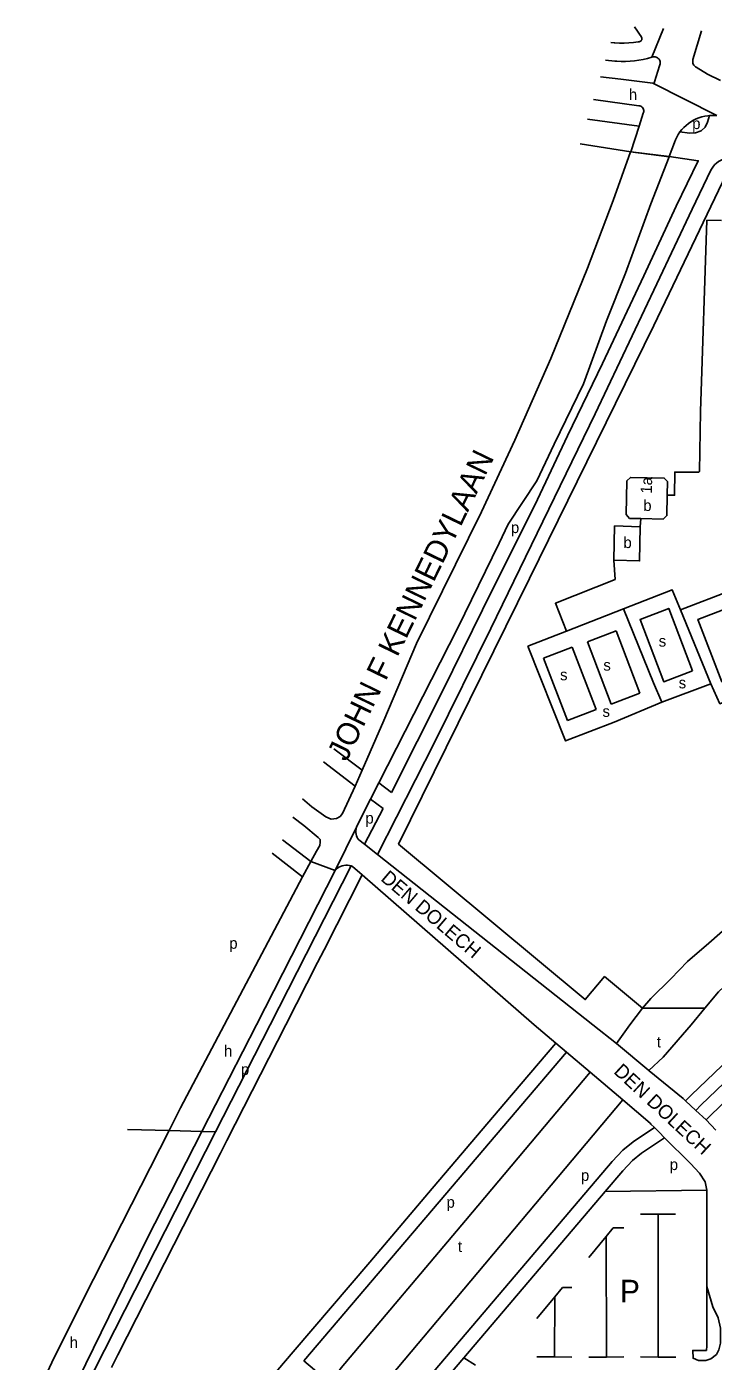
# Model space of a CAD drawing. Extents: x 161494 to 163033, y 383688 to 384862.
# Drawn here: x 161560.3 to 161805.5, y 384379.7 to 384856.8 of the extents above; entities that cross this region are included whole.
import ezdxf

# ---------------------------------------------------------------- set-up
doc = ezdxf.new("R2010")
doc.units = 0
for name, color, linetype in [('BLT_Basislijn', 7, 'Continuous'), ('BLT_Bebouwing', 7, 'Continuous'), ('BLT_Centroide', 7, 'Continuous'), ('BLT_Huisnummer', 7, 'Continuous'), ('BLT_Straatnaam', 7, 'Continuous'), ('BLT_Straatnaam_hoofdweg', 7, 'Continuous'), ('BLT_Tekst_parkeren', 7, 'Continuous'), ('BLT_Vlakafsluiter', 7, 'Continuous')]:
    doc.layers.add(name, color=color, linetype=linetype)

msp = doc.modelspace()

# ---------------------------------------------------------------- linework, layer by layer
at = {"layer": 'BLT_Basislijn'}
for p, q in [((161779.17, 384854.17), (161779.74, 384853.35)), ((161798.25, 384845.07), (161801.3, 384855.35)), ((161768.89, 384851.2), (161770.12, 384851.08)), ((161766.99, 384844.85), (161770.4, 384844.56)), ((161786.33, 384842.83), (161784.51, 384837.11)), ((161762.76, 384830.78), (161778.88, 384828.53)), ((161780.48, 384825.89), (161778.98, 384821.27)), ((161760.64, 384823.71), (161778.98, 384821.27)), ((161778.98, 384821.27), (161776.02, 384812.08)), ((161791.65, 384815.42), (161789.72, 384810.39)), ((161757.99, 384814.89), (161776.02, 384812.08)), ((161776, 384812.03), (161769.81, 384794.69)), ((161776.02, 384812.08), (161776, 384812.03)), ((161789.7, 384810.34), (161783.24, 384793.49)), ((161789.72, 384810.39), (161789.7, 384810.34)), ((161784.28, 384750), (161810.11, 384804.01)), ((161798.01, 384791.56), (161804.65, 384805.55)), ((161783.24, 384793.49), (161774.11, 384768.68)), ((161792.26, 384792.71), (161780.69, 384767.81)), ((161798.01, 384791.56), (161785.37, 384764.86)), ((161739.86, 384659.59), (161784.28, 384750)), ((161723.06, 384648.3), (161742.73, 384687.85)), ((161726.01, 384641.71), (161748.8, 384688.54)), ((161779.43, 384678.07), (161779.62, 384680.98)), ((161811.74, 384655.29), (161793.85, 384648.38)), ((161773.49, 384648.66), (161753.04, 384640.72)), ((161773.49, 384648.66), (161784.17, 384622.22)), ((161793.85, 384648.38), (161804.61, 384621.95)), ((161686.08, 384586.53), (161714.22, 384641.88)), ((161770.81, 384640.85), (161760.56, 384636.95)), ((161779.3, 384618.55), (161770.81, 384640.85)), ((161755.14, 384634.99), (161744.9, 384631.08)), ((161763.64, 384612.68), (161755.14, 384634.99)), ((161760.56, 384636.95), (161769.05, 384614.65)), ((161744.9, 384631.08), (161753.39, 384608.78)), ((161769.05, 384614.65), (161779.3, 384618.55)), ((161770.09, 384608.25), (161787.19, 384615.3)), ((161753.39, 384608.78), (161763.64, 384612.68)), ((161670.01, 384598.69), (161680.05, 384590.98)), ((161666.31, 384593.96), (161677.54, 384585.27)), ((161677.54, 384585.27), (161680.05, 384590.98)), ((161683.1, 384580.67), (161686.08, 384586.53)), ((161686.08, 384586.53), (161690.53, 384583.1)), ((161677.54, 384585.27), (161673.11, 384575.6)), ((161658.83, 384580.84), (161662.16, 384577.93)), ((161678.33, 384571.22), (161683.1, 384580.67)), ((161687.6, 384577.29), (161680.87, 384564.52)), ((161683.1, 384580.67), (161687.6, 384577.29)), ((161655.34, 384574.19), (161659.2, 384571.26)), ((161678.33, 384571.22), (161678.05, 384570.66)), ((161651.65, 384566.08), (161661.72, 384558.44)), ((161678.87, 384566.1), (161680.87, 384564.52)), ((161680.87, 384564.52), (161685.54, 384560.83)), ((161647.98, 384561.33), (161658.72, 384552.92)), ((161661.72, 384558.44), (161658.72, 384552.92)), ((161685.54, 384560.83), (161762.52, 384500)), ((161670.48, 384555.12), (161642.33, 384500)), ((161676.12, 384556.78), (161647.22, 384500)), ((161680.09, 384553.57), (161666.47, 384526.8)), ((161676.67, 384556.55), (161676.12, 384556.78)), ((161680.09, 384553.57), (161676.67, 384556.55)), ((161741.54, 384500), (161680.09, 384553.57)), ((161658.72, 384552.92), (161615.23, 384470.27)), ((161666.47, 384526.8), (161664.14, 384522.22)), ((161664.14, 384522.22), (161652.83, 384500)), ((161780.24, 384505.95), (161775.73, 384500)), ((161802.53, 384505.89), (161797.62, 384500)), ((161647.22, 384500), (161627.72, 384461.69)), ((161652.83, 384500), (161631.79, 384458.66)), ((161749.28, 384493.44), (161741.54, 384500)), ((161762.52, 384500), (161770.98, 384493.29)), ((161775.73, 384500), (161770.98, 384493.29)), ((161749.28, 384493.44), (161730.75, 384471.65)), ((161753.09, 384490.21), (161749.28, 384493.44)), ((161782.51, 384483.68), (161770.98, 384493.29)), ((161753.09, 384490.21), (161707.6, 384436.66)), ((161761.58, 384483.02), (161753.09, 384490.21)), ((161761.58, 384483.02), (161716.98, 384430.06)), ((161773.15, 384473.21), (161761.58, 384483.02)), ((161782.62, 384483.6), (161782.51, 384483.68)), ((161782.62, 384483.6), (161794.75, 384473.61)), ((161773.15, 384473.21), (161716.45, 384405.5)), ((161782.91, 384464.8), (161773.15, 384473.21)), ((161794.75, 384473.61), (161795.64, 384472.79)), ((161795.64, 384472.79), (161799.32, 384469.4)), ((161730.75, 384471.65), (161703.79, 384439.89)), ((161799.32, 384469.4), (161802.96, 384465.98)), ((161802.96, 384465.98), (161806.43, 384462.37)), ((161627.72, 384461.69), (161580.87, 384369.61)), ((161631.79, 384458.66), (161629.46, 384454.07)), ((161788.13, 384459.63), (161786.13, 384461.63)), ((161797.23, 384450.54), (161788.13, 384459.63)), ((161629.46, 384454.07), (161592.77, 384381.97)), ((161797.38, 384450.39), (161797.23, 384450.54)), ((161800.62, 384446.93), (161797.38, 384450.39)), ((161703.79, 384439.89), (161682.86, 384415.19)), ((161803.19, 384440.85), (161803.2, 384406.39)), ((161707.6, 384436.66), (161659.3, 384379.87)), ((161779.55, 384432.35), (161785.83, 384432.32)), ((161785.81, 384381.23), (161785.83, 384432.32)), ((161785.83, 384432.32), (161791.99, 384432.28)), ((161761.11, 384416.83), (161767.24, 384424.37)), ((161767.24, 384424.37), (161769.76, 384427.47)), ((161767.32, 384381.23), (161767.24, 384424.37)), ((161769.76, 384427.47), (161773.55, 384427.47)), ((161682.86, 384415.19), (161655.48, 384383.11)), ((161716.45, 384405.5), (161680.09, 384362.34)), ((161748.86, 384402.77), (161751.6, 384406.12)), ((161751.6, 384406.12), (161755, 384406.12)), ((161742.51, 384395.01), (161748.86, 384402.77)), ((161748.78, 384381.24), (161748.86, 384402.77)), ((161592.77, 384381.97), (161590.5, 384377.51)), ((161742.51, 384381.27), (161748.78, 384381.24)), ((161748.78, 384381.24), (161755.04, 384381.22)), ((161761.08, 384381.22), (161767.32, 384381.23)), ((161767.32, 384381.23), (161773.56, 384381.24)), ((161779.54, 384381.24), (161785.81, 384381.23)), ((161785.81, 384381.23), (161792.08, 384381.23)), ((161659.3, 384379.87), (161668.38, 384372.17)), ((161720.58, 384378.35), (161716.39, 384380.97))]:
    msp.add_line(p, q, dxfattribs=at)
for points in [[(161777.42, 384856.83), (161778.43, 384855.26), (161779.17, 384854.17)], [(161778.73, 384851.4), (161777.06, 384851.17), (161775.37, 384851.03), (161773.68, 384850.96), (161771.99, 384850.97), (161770.3, 384851.07), (161770.12, 384851.08)], [(161778.73, 384851.4), (161779.04, 384851.41), (161779.33, 384851.49), (161779.6, 384851.65), (161779.81, 384851.87), (161779.95, 384852.14), (161780.03, 384852.44), (161780.02, 384852.75), (161779.93, 384853.04), (161779.74, 384853.35)], [(161783.51, 384845.96), (161781.99, 384845.5), (161780.46, 384845.12), (161778.91, 384844.82), (161777.35, 384844.6), (161775.77, 384844.45), (161774.19, 384844.39), (161772.61, 384844.4), (161771.04, 384844.5), (161770.4, 384844.56)], [(161783.51, 384845.96), (161783.92, 384846.08), (161784.34, 384846.11), (161784.76, 384846.07), (161785.17, 384845.94), (161785.54, 384845.75), (161785.88, 384845.49), (161786.15, 384845.16), (161786.37, 384844.8), (161786.51, 384844.4), (161786.57, 384843.98), (161786.55, 384843.55), (161786.46, 384843.14), (161786.33, 384842.83)], [(161798.25, 384845.07), (161798.16, 384844.66), (161798.16, 384844.24), (161798.23, 384843.82), (161798.38, 384843.42), (161798.6, 384843.06), (161798.88, 384842.75), (161799.22, 384842.49), (161799.38, 384842.4)], [(161808.06, 384837.6), (161803.46, 384839.8), (161799.38, 384842.4)], [(161783.92, 384836.6), (161772.48, 384838.07), (161765.21, 384838.95)], [(161783.92, 384836.6), (161784.12, 384836.59), (161784.3, 384836.65), (161784.43, 384836.78), (161784.51, 384836.96), (161784.51, 384837.11)], [(161778.88, 384828.53), (161779.26, 384828.49), (161779.62, 384828.37), (161779.95, 384828.18), (161780.23, 384827.92), (161780.45, 384827.61), (161780.6, 384827.26), (161780.67, 384826.89), (161780.67, 384826.51), (161780.59, 384826.14), (161780.48, 384825.89)], [(161793.62, 384819.19), (161796.96, 384818.75), (161799.14, 384818.84), (161801.18, 384819.58), (161802.57, 384820.89), (161803.47, 384822.65), (161804.12, 384825.06)], [(161804.12, 384825.06), (161803.52, 384825.01), (161802.46, 384824.84), (161801.42, 384824.59), (161800.39, 384824.27), (161799.4, 384823.87), (161798.43, 384823.39), (161797.51, 384822.85), (161796.63, 384822.24), (161795.79, 384821.56), (161795.01, 384820.83), (161794.29, 384820.04), (161793.62, 384819.19)], [(161806.74, 384825.04), (161805.67, 384825.11), (161804.59, 384825.1), (161804.12, 384825.06)], [(161793.62, 384819.19), (161793.02, 384818.3), (161792.49, 384817.37), (161792.03, 384816.4), (161791.65, 384815.42)], [(161789.72, 384810.39), (161800.15, 384808.92), (161792.26, 384792.71)], [(161804.65, 384805.55), (161805.07, 384806.26), (161805.56, 384806.92), (161806.11, 384807.53), (161806.71, 384808.08), (161807.37, 384808.58), (161808.07, 384809), (161808.81, 384809.36), (161809.59, 384809.64), (161810.38, 384809.85), (161811.19, 384809.98), (161812.01, 384810.03), (161812.83, 384809.99), (161813.17, 384809.96)], [(161722.69, 384683.39), (161734.6, 384709.01), (161747.45, 384738.15), (161760.6, 384770.45), (161769.81, 384794.69)], [(161800.97, 384719.21), (161803.24, 384787.61), (161808.49, 384787.5)], [(161732.28, 384678.98), (161742.43, 384694.43), (161748.62, 384707.62), (161759.2, 384729.13), (161767.35, 384751.68), (161774.11, 384768.68)], [(161742.73, 384687.85), (161753.48, 384710.57), (161765.96, 384736.41), (161780.69, 384767.81)], [(161748.8, 384688.54), (161763.36, 384718.37), (161785.37, 384764.86)], [(161800.97, 384719.21), (161800.55, 384697.75), (161800.35, 384697.51), (161794.03, 384697.51)], [(161794.03, 384697.51), (161791.76, 384697.62), (161791.71, 384689.32), (161789.1, 384689.38)], [(161680.05, 384590.98), (161687.88, 384608.81), (161699.49, 384636.28), (161722.69, 384683.39)], [(161714.22, 384641.88), (161729.04, 384672.23), (161732.28, 384678.98)], [(161753.04, 384640.72), (161749.14, 384650.71), (161770.42, 384659.22), (161770.02, 384666.11)], [(161780.24, 384505.95), (161766.67, 384517.26), (161759.76, 384509.02), (161693.1, 384564.6), (161739.86, 384659.59)], [(161773.49, 384648.66), (161790.84, 384655.47), (161793.85, 384648.38)], [(161798.09, 384626.55), (161789.59, 384648.86), (161779.35, 384644.95), (161787.84, 384622.65), (161798.09, 384626.55)], [(161818.77, 384626.55), (161810.27, 384648.86), (161800.03, 384644.95), (161808.52, 384622.65), (161818.77, 384626.55)], [(161690.53, 384583.1), (161708.85, 384619.5), (161723.06, 384648.3)], [(161685.54, 384560.83), (161705.9, 384600.94), (161726.01, 384641.71)], [(161753.04, 384640.72), (161739.21, 384635.35)], [(161739.21, 384635.35), (161752.68, 384601.47), (161770.09, 384608.25)], [(161784.17, 384622.22), (161787.19, 384615.3)], [(161787.19, 384615.3), (161804.61, 384621.95)], [(161804.61, 384621.95), (161807.86, 384614.76), (161825.19, 384621.75)], [(161662.16, 384577.93), (161667.15, 384574.36), (161669.02, 384573.56), (161670.9, 384573.72), (161672.22, 384574.48), (161673.11, 384575.6)], [(161939.88, 384575.55), (161933.16, 384569.9), (161930.17, 384567.61), (161923.57, 384564.05), (161880.13, 384543.25), (161875.48, 384541.33), (161869.42, 384539.18), (161866.4, 384538.3), (161863.11, 384537.18), (161860.29, 384535.54), (161858.06, 384533.63), (161845.78, 384521.31), (161828.11, 384504.08), (161797.59, 384474.82), (161795.64, 384472.79)], [(161659.2, 384571.26), (161664.42, 384567.02), (161665.06, 384566.21), (161665.11, 384565.25), (161664.92, 384564.12), (161663.8, 384562.07), (161661.72, 384558.44)], [(161678.05, 384570.66), (161677.93, 384570.04), (161677.86, 384569.42), (161677.86, 384568.79), (161677.94, 384568.17), (161678.1, 384567.57), (161678.33, 384566.99), (161678.47, 384566.72)], [(161678.47, 384566.72), (161678.65, 384566.37), (161678.87, 384566.1)], [(161676.12, 384556.78), (161675.47, 384556.96), (161674.85, 384557.05), (161674.21, 384557.06), (161673.58, 384556.99), (161672.97, 384556.85), (161672.37, 384556.62), (161671.81, 384556.32), (161671.3, 384555.96), (161670.83, 384555.53), (161670.48, 384555.12)], [(161839, 384554.76), (161830.84, 384549.88), (161826.82, 384547.41), (161819.08, 384541.83), (161811.82, 384536.14), (161803.97, 384529.16), (161796.27, 384522.62)], [(161846.45, 384540.79), (161834.11, 384532.91), (161826.23, 384527.48), (161822.52, 384524.85), (161815.04, 384518.96), (161807.43, 384511.78), (161802.53, 384505.89)], [(161872.55, 384534.98), (161870.96, 384534.42), (161867.9, 384533.53), (161865.19, 384532.6), (161863.19, 384531.45), (161861.46, 384529.96), (161849.3, 384517.75), (161831.58, 384500.48), (161801.12, 384471.28), (161799.32, 384469.4)], [(161874.22, 384530.27), (161872.5, 384529.66), (161869.41, 384528.76), (161867.27, 384528.03), (161866.1, 384527.35), (161864.87, 384526.3), (161852.81, 384514.2), (161835.06, 384496.89), (161804.66, 384467.74), (161802.96, 384465.98)], [(161796.27, 384522.62), (161790.37, 384516.38), (161783.16, 384509.36), (161780.24, 384505.95)], [(161642.33, 384500), (161622.83, 384461.81)], [(161797.62, 384500), (161787.59, 384488.48), (161782.51, 384483.68)], [(161611.1, 384462.16), (161615.23, 384470.27)], [(161784.52, 384463.24), (161776.84, 384458.17), (161773.19, 384455.17), (161769.45, 384451.16), (161696.02, 384364.72), (161693.68, 384361.06), (161692.37, 384357.61), (161691.36, 384353.54), (161691.33, 384353.08)], [(161784.52, 384463.24), (161783.24, 384464.52), (161782.91, 384464.8)], [(161786.13, 384461.63), (161784.52, 384463.24)], [(161560.26, 384360.04), (161565.01, 384370.29), (161569.26, 384379.28), (161580.75, 384402.53), (161611.1, 384462.16)], [(161622.83, 384461.81), (161603.33, 384423.62), (161581.43, 384378.84), (161569.05, 384353.83)], [(161788.13, 384459.63), (161779.82, 384454.14), (161776.62, 384451.52), (161773.18, 384447.84), (161766.87, 384440.41)], [(161800.62, 384446.93), (161802.65, 384443.87), (161803.19, 384440.85)], [(161766.87, 384440.41), (161716.39, 384380.97)], [(161766.87, 384440.41), (161803.19, 384440.85)], [(161716.98, 384430.06), (161672.62, 384377.38), (161668.71, 384371.89)], [(161803.2, 384406.39), (161803.2, 384385.17), (161803.08, 384383.57), (161798.15, 384383.59), (161798.3, 384380.78), (161800.29, 384379.98), (161802.89, 384379.98), (161804.68, 384380.58), (161806.68, 384382.18), (161807.47, 384383.77), (161808.07, 384386.17), (161808.08, 384389.36), (161808.06, 384391.6), (161807.25, 384395.24), (161805.4, 384399.17), (161803.2, 384406.39)], [(161655.48, 384383.11), (161649.95, 384376.68), (161647.82, 384373.92), (161645.76, 384371.11), (161643.77, 384368.26), (161641.84, 384365.36), (161639.98, 384362.42), (161638.18, 384359.44), (161636.69, 384356.84)], [(161716.39, 384380.97), (161700.05, 384361.74), (161698.17, 384358.8), (161697.15, 384356.12), (161696.67, 384354.18)]]:
    msp.add_lwpolyline(points, dxfattribs=at)
at = {"layer": 'BLT_Bebouwing'}
msp.add_line((161789.2, 384694.18), (161789.1, 384689.38), dxfattribs=at)
for points in [[(161779.62, 384680.98), (161775.61, 384681.06), (161774.34, 384682.38), (161774.6, 384694.43), (161775.93, 384695.71), (161787.99, 384695.45), (161789.2, 384694.18)], [(161789.1, 384689.38), (161788.94, 384682.04), (161787.65, 384680.8), (161779.62, 384680.98)], [(161779.43, 384678.07), (161770.24, 384678.33), (161770.02, 384666.11)], [(161770.02, 384666.11), (161779.21, 384665.85), (161779.43, 384678.07)]]:
    msp.add_lwpolyline(points, dxfattribs=at)
at = {"layer": 'BLT_Vlakafsluiter'}
for p, q in [((161787.78, 384856.19), (161783.51, 384845.96)), ((161783.92, 384836.6), (161806.74, 384825.04)), ((161776, 384812.03), (161789.7, 384810.34)), ((161776.02, 384812.08), (161789.72, 384810.39)), ((161678.05, 384570.66), (161670.48, 384555.12)), ((161661.72, 384558.44), (161670.48, 384555.12)), ((161780.24, 384505.95), (161802.53, 384505.89)), ((161596.26, 384462.6), (161611.1, 384462.16)), ((161611.1, 384462.16), (161622.83, 384461.81)), ((161622.83, 384461.81), (161627.72, 384461.69))]:
    msp.add_line(p, q, dxfattribs=at)

# ---------------------------------------------------------------- texts
at = {"layer": 'BLT_Centroide'}
for s, p in [('h', (161775.34, 384830.57)), ('p', (161797.97, 384820.23)), ('b', (161780.49, 384683.68)), ('p', (161733.22, 384675.79)), ('b', (161773.41, 384670.44)), ('s', (161786.01, 384635.2)), ('s', (161766.24, 384626.6)), ('s', (161750.78, 384623.16)), ('s', (161793.15, 384620.27)), ('s', (161765.94, 384610.08)), ('p', (161681.24, 384571.92)), ('p', (161632.61, 384527.18)), ('h', (161630.72, 384488.66)), ('t', (161785.33, 384491.91)), ('p', (161636.77, 384482.09)), ('p', (161789.96, 384448.07)), ('p', (161758.23, 384444.21)), ('p', (161710.22, 384434.6)), ('t', (161714.3, 384418.77)), ('h', (161575.6, 384384.44))]:
    msp.add_text(s, height=4, dxfattribs=at).set_placement(p)
at = {"layer": 'BLT_Huisnummer'}
msp.add_text('1a', height=4, rotation=88.8879, dxfattribs=at).set_placement((161783.58, 384689.86))
at = {"layer": 'BLT_Straatnaam'}
for rotation, p in [(319.6222, (161686.43, 384551.82)), (317.1985, (161769.64, 384482.93))]:
    msp.add_text('DEN DOLECH', height=5, rotation=rotation, dxfattribs=at).set_placement(p)
at = {"layer": 'BLT_Straatnaam_hoofdweg'}
msp.add_text('JOHN F KENNEDYLAAN', height=8, rotation=64.128, dxfattribs=at).set_placement((161674.5, 384593.77))
at = {"layer": 'BLT_Tekst_parkeren'}
msp.add_text('P', height=8, dxfattribs=at).set_placement((161772.17, 384400.83))

doc.saveas('drawing.dxf')
